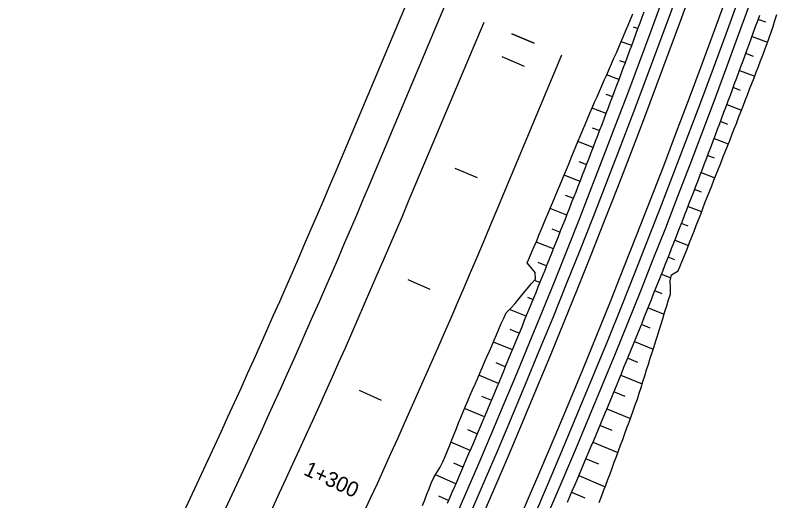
# Model space of a CAD drawing. Extents: x 6503541 to 6503743, y 5888004 to 5888145.
# Drawn here: x 6503701.128 to 6503702.659, y 5888111.328 to 5888112.29 of the extents above; entities that cross this region are included whole.
import ezdxf

# ---------------------------------------------------------------- set-up
doc = ezdxf.new("R2010")
doc.units = 0
doc.layers.add('12', color=7, linetype='Continuous')

msp = doc.modelspace()

# ---------------------------------------------------------------- linework, layer by layer
at = {"layer": '12'}
for p, q in [((6503701.7627, 5888111.9819), (6503701.9121, 5888112.3369)), ((6503701.829, 5888111.954), (6503701.9785, 5888112.309)), ((6503701.9064, 5888111.9214), (6503702.0561, 5888112.2767)), ((6503702.614, 5888112.2766), (6503702.5989, 5888112.2821)), ((6503702.3512, 5888112.2675), (6503702.3608, 5888112.264)), ((6503702.5866, 5888112.2482), (6503702.6174, 5888112.237)), ((6503702.3483, 5888112.2302), (6503702.3275, 5888112.2379)), ((6503702.08, 5888111.9008), (6503702.21, 5888112.2118)), ((6503702.5895, 5888112.2088), (6503702.5742, 5888112.2144)), ((6503702.3244, 5888112.2007), (6503702.3357, 5888112.1965)), ((6503702.5618, 5888112.1806), (6503702.5919, 5888112.1695)), ((6503702.3231, 5888112.1627), (6503702.2986, 5888112.1719)), ((6503702.2973, 5888112.134), (6503702.3105, 5888112.1291)), ((6503702.5641, 5888112.1414), (6503702.5493, 5888112.1469)), ((6503702.2977, 5888112.0954), (6503702.2697, 5888112.106)), ((6503702.5367, 5888112.1131), (6503702.5658, 5888112.1023)), ((6503702.5384, 5888112.074), (6503702.5241, 5888112.0794)), ((6503702.2702, 5888112.0674), (6503702.2849, 5888112.0617)), ((6503702.5114, 5888112.0457), (6503702.5396, 5888112.0351)), ((6503702.272, 5888112.0281), (6503702.2418, 5888112.0397)), ((6503702.5125, 5888112.0068), (6503702.4987, 5888112.0121)), ((6503702.2436, 5888112.0005), (6503702.2591, 5888111.9945)), ((6503702.246, 5888111.961), (6503702.2144, 5888111.9733)), ((6503702.4858, 5888111.9784), (6503702.513, 5888111.968)), ((6503702.4863, 5888111.9397), (6503702.4729, 5888111.9448)), ((6503702.2168, 5888111.9337), (6503702.233, 5888111.9274)), ((6503702.2198, 5888111.8939), (6503702.1868, 5888111.9069)), ((6503702.46, 5888111.9112), (6503702.4867, 5888111.9009)), ((6503702.4604, 5888111.8724), (6503702.4469, 5888111.8777)), ((6503702.1898, 5888111.8671), (6503702.2066, 5888111.8604)), ((6503702.4339, 5888111.8441), (6503702.4607, 5888111.8336)), ((6503702.1933, 5888111.827), (6503702.159, 5888111.8406)), ((6503702.1625, 5888111.8005), (6503702.1799, 5888111.7935)), ((6503702.434, 5888111.8054), (6503702.4207, 5888111.8106)), ((6503702.4075, 5888111.7771), (6503702.426, 5888111.7698)), ((6503702.1665, 5888111.7601), (6503702.1555, 5888111.7646)), ((6503702.4087, 5888111.7379), (6503702.3942, 5888111.7437)), ((6503702.1421, 5888111.7312), (6503702.153, 5888111.7268)), ((6503702.1395, 5888111.6934), (6503702.1063, 5888111.7069)), ((6503702.3808, 5888111.7103), (6503702.4126, 5888111.6975)), ((6503702.3846, 5888111.6699), (6503702.3674, 5888111.6769)), ((6503702.1072, 5888111.6677), (6503702.1258, 5888111.6601)), ((6503702.3539, 5888111.6435), (6503702.391, 5888111.6284)), ((6503702.1122, 5888111.6268), (6503702.0743, 5888111.6424)), ((6503702.0792, 5888111.6015), (6503702.0984, 5888111.5935)), ((6503702.3602, 5888111.602), (6503702.3403, 5888111.6101)), ((6503702.0846, 5888111.5603), (6503702.0456, 5888111.5765)), ((6503702.3267, 5888111.5768), (6503702.3691, 5888111.5594)), ((6503702.3355, 5888111.5342), (6503702.313, 5888111.5435)), ((6503702.051, 5888111.5353), (6503702.0707, 5888111.5271)), ((6503702.0567, 5888111.4939), (6503702.0172, 5888111.5106)), ((6503702.2993, 5888111.5102), (6503702.3458, 5888111.4909)), ((6503702.3094, 5888111.467), (6503702.2854, 5888111.477)), ((6503702.0232, 5888111.469), (6503702.0427, 5888111.4607)), ((6503702.0286, 5888111.4276), (6503701.9903, 5888111.444)), ((6503702.2716, 5888111.4438), (6503702.3209, 5888111.4231)), ((6503701.9956, 5888111.4026), (6503702.0145, 5888111.3945)), ((6503702.283, 5888111.3999), (6503702.2576, 5888111.4106)), ((6503702.0002, 5888111.3614), (6503701.9596, 5888111.379)), ((6503702.2436, 5888111.3775), (6503702.2957, 5888111.3553)), ((6503701.9655, 5888111.3373), (6503701.9859, 5888111.3284)), ((6503702.2561, 5888111.333), (6503702.2295, 5888111.3443))]:
    msp.add_line(p, q, dxfattribs=at)
for points in [[(6503701.9342, 5888111.3183), (6503701.9384, 5888111.3295), (6503701.9428, 5888111.3406), (6503701.9473, 5888111.3516), (6503701.9514, 5888111.3628), (6503701.9563, 5888111.3736), (6503701.9625, 5888111.3839), (6503701.9687, 5888111.3942), (6503701.9744, 5888111.4047), (6503701.9788, 5888111.4157), (6503701.9833, 5888111.4268), (6503701.9878, 5888111.4378), (6503701.9923, 5888111.4488), (6503701.9967, 5888111.4598), (6503702.0012, 5888111.4709), (6503702.0056, 5888111.4819), (6503702.0101, 5888111.493), (6503702.0145, 5888111.504), (6503702.0191, 5888111.515), (6503702.0237, 5888111.526), (6503702.0285, 5888111.5369), (6503702.0333, 5888111.5478), (6503702.038, 5888111.5586), (6503702.0427, 5888111.5696), (6503702.0473, 5888111.5806), (6503702.0521, 5888111.5915), (6503702.0569, 5888111.6024), (6503702.0617, 5888111.6133), (6503702.0664, 5888111.6242), (6503702.0711, 5888111.6351), (6503702.0759, 5888111.646), (6503702.0806, 5888111.6569), (6503702.0853, 5888111.6679), (6503702.09, 5888111.6788), (6503702.0948, 5888111.6897), (6503702.0995, 5888111.7006), (6503702.1092, 5888111.7096), (6503702.1172, 5888111.7191), (6503702.1253, 5888111.7287), (6503702.1334, 5888111.7383), (6503702.1414, 5888111.7479), (6503702.1495, 5888111.7575), (6503702.1576, 5888111.7671), (6503702.1568, 5888111.7802), (6503702.1415, 5888111.7992), (6503702.1461, 5888111.8102), (6503702.1508, 5888111.8211), (6503702.1554, 5888111.8321), (6503702.1601, 5888111.8431), (6503702.1646, 5888111.854), (6503702.1693, 5888111.865), (6503702.1739, 5888111.876), (6503702.1785, 5888111.887), (6503702.1831, 5888111.8979), (6503702.1877, 5888111.9089), (6503702.1923, 5888111.9199), (6503702.1969, 5888111.9309), (6503702.2014, 5888111.9419), (6503702.206, 5888111.9529), (6503702.2105, 5888111.9639), (6503702.2151, 5888111.9749), (6503702.2196, 5888111.9859), (6503702.2242, 5888111.9969), (6503702.2287, 5888112.0079), (6503702.2332, 5888112.0189), (6503702.2378, 5888112.03), (6503702.2423, 5888112.041), (6503702.2468, 5888112.052), (6503702.2514, 5888112.063), (6503702.2559, 5888112.074), (6503702.2605, 5888112.085), (6503702.2652, 5888112.096), (6503702.27, 5888112.1069), (6503702.2749, 5888112.1178), (6503702.2797, 5888112.1287), (6503702.2844, 5888112.1396), (6503702.2892, 5888112.1505), (6503702.294, 5888112.1614), (6503702.2988, 5888112.1724), (6503702.3037, 5888112.1833), (6503702.3084, 5888112.1942), (6503702.3131, 5888112.2052), (6503702.3179, 5888112.2161), (6503702.3227, 5888112.227), (6503702.3275, 5888112.238), (6503702.3323, 5888112.2489), (6503702.337, 5888112.2598), (6503702.3415, 5888112.2709), (6503702.346, 5888112.2819), (6503702.3505, 5888112.2929)], [(6503701.9836, 5888111.3229), (6503701.9883, 5888111.3338), (6503701.993, 5888111.3448), (6503701.9978, 5888111.3557), (6503702.0025, 5888111.3667), (6503702.0072, 5888111.3776), (6503702.0119, 5888111.3886), (6503702.0166, 5888111.3995), (6503702.0213, 5888111.4105), (6503702.026, 5888111.4215), (6503702.0307, 5888111.4324), (6503702.0354, 5888111.4434), (6503702.04, 5888111.4544), (6503702.0447, 5888111.4654), (6503702.0493, 5888111.4763), (6503702.054, 5888111.4873), (6503702.0586, 5888111.4983), (6503702.0632, 5888111.5093), (6503702.0679, 5888111.5203), (6503702.0725, 5888111.5313), (6503702.0771, 5888111.5423), (6503702.0817, 5888111.5533), (6503702.0863, 5888111.5643), (6503702.0909, 5888111.5753), (6503702.0954, 5888111.5864), (6503702.1, 5888111.5974), (6503702.1046, 5888111.6084), (6503702.1091, 5888111.6194), (6503702.1137, 5888111.6304), (6503702.1182, 5888111.6415), (6503702.1227, 5888111.6525), (6503702.1273, 5888111.6635), (6503702.1318, 5888111.6746), (6503702.1363, 5888111.6856), (6503702.1408, 5888111.6967), (6503702.1453, 5888111.7077), (6503702.1498, 5888111.7188), (6503702.1543, 5888111.7298), (6503702.1588, 5888111.7409), (6503702.1632, 5888111.7519), (6503702.1677, 5888111.763), (6503702.1721, 5888111.7741), (6503702.1766, 5888111.7851), (6503702.181, 5888111.7962), (6503702.1854, 5888111.8073), (6503702.1899, 5888111.8183), (6503702.1943, 5888111.8294), (6503702.1987, 5888111.8405), (6503702.2031, 5888111.8516), (6503702.2075, 5888111.8627), (6503702.2119, 5888111.8738), (6503702.2163, 5888111.8849), (6503702.2206, 5888111.896), (6503702.225, 5888111.9071), (6503702.2293, 5888111.9182), (6503702.2337, 5888111.9293), (6503702.238, 5888111.9404), (6503702.2424, 5888111.9515), (6503702.2467, 5888111.9626), (6503702.251, 5888111.9737), (6503702.2553, 5888111.9849), (6503702.2596, 5888111.996), (6503702.2639, 5888112.0071), (6503702.2682, 5888112.0182), (6503702.2725, 5888112.0294), (6503702.2768, 5888112.0405), (6503702.281, 5888112.0516), (6503702.2853, 5888112.0628), (6503702.2896, 5888112.0739), (6503702.2938, 5888112.0851), (6503702.298, 5888112.0962), (6503702.3023, 5888112.1074), (6503702.3065, 5888112.1185), (6503702.3107, 5888112.1297), (6503702.3149, 5888112.1408), (6503702.3191, 5888112.152), (6503702.3233, 5888112.1632), (6503702.3275, 5888112.1743), (6503702.3317, 5888112.1855), (6503702.3358, 5888112.1967), (6503702.34, 5888112.2079), (6503702.3442, 5888112.219), (6503702.3483, 5888112.2302), (6503702.3524, 5888112.2414), (6503702.3566, 5888112.2526), (6503702.3607, 5888112.2638), (6503702.3648, 5888112.275), (6503702.3689, 5888112.2862), (6503702.373, 5888112.2974)], [(6503702.2212, 5888111.325), (6503702.226, 5888111.3361), (6503702.2307, 5888111.3472), (6503702.2354, 5888111.3583), (6503702.2402, 5888111.3694), (6503702.2449, 5888111.3805), (6503702.2496, 5888111.3916), (6503702.2543, 5888111.4028), (6503702.259, 5888111.4139), (6503702.2637, 5888111.425), (6503702.2683, 5888111.4361), (6503702.273, 5888111.4473), (6503702.2777, 5888111.4584), (6503702.2823, 5888111.4695), (6503702.287, 5888111.4807), (6503702.2916, 5888111.4918), (6503702.2962, 5888111.503), (6503702.3009, 5888111.5141), (6503702.3055, 5888111.5253), (6503702.3101, 5888111.5364), (6503702.3147, 5888111.5476), (6503702.3193, 5888111.5588), (6503702.3239, 5888111.5699), (6503702.3285, 5888111.5811), (6503702.333, 5888111.5923), (6503702.3376, 5888111.6034), (6503702.3422, 5888111.6146), (6503702.3467, 5888111.6258), (6503702.3513, 5888111.637), (6503702.3558, 5888111.6482), (6503702.3603, 5888111.6594), (6503702.3649, 5888111.6706), (6503702.3694, 5888111.6818), (6503702.3739, 5888111.693), (6503702.3784, 5888111.7042), (6503702.3829, 5888111.7154), (6503702.3873, 5888111.7266), (6503702.3918, 5888111.7378), (6503702.3963, 5888111.749), (6503702.4008, 5888111.7602), (6503702.4052, 5888111.7714), (6503702.4097, 5888111.7827), (6503702.4141, 5888111.7939), (6503702.4185, 5888111.8051), (6503702.423, 5888111.8163), (6503702.4274, 5888111.8276), (6503702.4318, 5888111.8388), (6503702.4362, 5888111.8501), (6503702.4406, 5888111.8613), (6503702.445, 5888111.8726), (6503702.4493, 5888111.8838), (6503702.4537, 5888111.8951), (6503702.4581, 5888111.9063), (6503702.4624, 5888111.9176), (6503702.4668, 5888111.9288), (6503702.4711, 5888111.9401), (6503702.4755, 5888111.9514), (6503702.4798, 5888111.9626), (6503702.4841, 5888111.9739), (6503702.4884, 5888111.9852), (6503702.4927, 5888111.9965), (6503702.497, 5888112.0077), (6503702.5013, 5888112.019), (6503702.5056, 5888112.0303), (6503702.5099, 5888112.0416), (6503702.5141, 5888112.0529), (6503702.5184, 5888112.0642), (6503702.5226, 5888112.0755), (6503702.5269, 5888112.0868), (6503702.5311, 5888112.0981), (6503702.5354, 5888112.1094), (6503702.5396, 5888112.1207), (6503702.5438, 5888112.132), (6503702.548, 5888112.1434), (6503702.5522, 5888112.1547), (6503702.5564, 5888112.166), (6503702.5606, 5888112.1773), (6503702.5647, 5888112.1886), (6503702.5689, 5888112.2), (6503702.5731, 5888112.2113), (6503702.5772, 5888112.2226), (6503702.5814, 5888112.234), (6503702.5855, 5888112.2453), (6503702.5896, 5888112.2567), (6503702.5938, 5888112.268), (6503702.5979, 5888112.2794), (6503702.602, 5888112.2907)], [(6503702.2841, 5888111.3244), (6503702.2884, 5888111.3358), (6503702.2926, 5888111.3471), (6503702.2969, 5888111.3585), (6503702.3011, 5888111.3698), (6503702.3054, 5888111.3812), (6503702.3096, 5888111.3925), (6503702.3138, 5888111.4039), (6503702.318, 5888111.4153), (6503702.3222, 5888111.4266), (6503702.3264, 5888111.438), (6503702.3306, 5888111.4494), (6503702.3348, 5888111.4608), (6503702.3389, 5888111.4721), (6503702.3431, 5888111.4835), (6503702.3473, 5888111.4949), (6503702.3514, 5888111.5063), (6503702.3555, 5888111.5177), (6503702.3595, 5888111.5292), (6503702.3632, 5888111.5407), (6503702.3669, 5888111.5523), (6503702.3705, 5888111.5639), (6503702.3742, 5888111.5754), (6503702.3779, 5888111.587), (6503702.3816, 5888111.5986), (6503702.3852, 5888111.6101), (6503702.3889, 5888111.6217), (6503702.3925, 5888111.6333), (6503702.3962, 5888111.6449), (6503702.3998, 5888111.6565), (6503702.4034, 5888111.668), (6503702.407, 5888111.6796), (6503702.4106, 5888111.6912), (6503702.4142, 5888111.7028), (6503702.4178, 5888111.7144), (6503702.4214, 5888111.726), (6503702.425, 5888111.7376), (6503702.4254, 5888111.7504), (6503702.4244, 5888111.7638), (6503702.4274, 5888111.7756), (6503702.4405, 5888111.7835), (6503702.445, 5888111.7947), (6503702.4496, 5888111.8059), (6503702.4541, 5888111.8171), (6503702.4586, 5888111.8283), (6503702.4631, 5888111.8395), (6503702.4675, 5888111.8508), (6503702.4719, 5888111.8621), (6503702.4763, 5888111.8733), (6503702.4807, 5888111.8846), (6503702.4849, 5888111.8959), (6503702.489, 5888111.9073), (6503702.4933, 5888111.9186), (6503702.4978, 5888111.9298), (6503702.5023, 5888111.9411), (6503702.5068, 5888111.9523), (6503702.5113, 5888111.9635), (6503702.5157, 5888111.9748), (6503702.5202, 5888111.986), (6503702.5246, 5888111.9972), (6503702.5291, 5888112.0085), (6503702.5335, 5888112.0197), (6503702.538, 5888112.031), (6503702.5424, 5888112.0422), (6503702.5468, 5888112.0535), (6503702.5512, 5888112.0648), (6503702.5556, 5888112.076), (6503702.56, 5888112.0873), (6503702.5644, 5888112.0986), (6503702.5688, 5888112.1098), (6503702.5732, 5888112.1211), (6503702.5775, 5888112.1324), (6503702.5819, 5888112.1437), (6503702.5862, 5888112.155), (6503702.5906, 5888112.1662), (6503702.5949, 5888112.1775), (6503702.5993, 5888112.1888), (6503702.6036, 5888112.2001), (6503702.6079, 5888112.2114), (6503702.6122, 5888112.2227), (6503702.6163, 5888112.2341), (6503702.6203, 5888112.2455), (6503702.6247, 5888112.2568), (6503702.6283, 5888112.2683), (6503702.6319, 5888112.2799), (6503702.6355, 5888112.2915)], [(6503702.1108, 5888112.2534), (6503702.1551, 5888112.2348)], [(6503702.1551, 5888112.2348), (6503702.1108, 5888112.2534)], [(6503702.1359, 5888112.189), (6503702.0916, 5888112.2076)], [(6503702.043, 5888111.9677), (6503701.9987, 5888111.9863)], [(6503701.9493, 5888111.7465), (6503701.9053, 5888111.7655)], [(6503701.8528, 5888111.5264), (6503701.809, 5888111.546)]]:
    msp.add_lwpolyline(points, dxfattribs=at)
for centre, radius, start, end in [((6503685.5719, 5888118.4473), 17.9412, 322.48762, 351.89568), ((6503685.5719, 5888118.4473), 17.9172, 324.73339, 351.89568), ((6503685.5719, 5888118.4473), 17.9652, 322.48762, 351.89568), ((6503685.5719, 5888118.4473), 18.0348, 322.48762, 351.89568), ((6503685.5719, 5888118.4473), 18.0588, 322.48762, 351.89568), ((6503685.5719, 5888118.4473), 18.0828, 324.58652, 351.89568), ((6503685.3946, 5888118.8742), 17.76, 330.69658, 337.1649), ((6503685.3946, 5888118.8742), 17.832, 330.69658, 337.1649), ((6503685.3946, 5888118.8742), 17.916, 330.69658, 337.1649), ((6503685.3946, 5888118.8742), 18.084, 330.69648, 337.31833)]:
    msp.add_arc(centre, radius, start, end, dxfattribs=at)

# ---------------------------------------------------------------- texts
msp.add_text('1+300', height=0.03, rotation=335.1776, dxfattribs=at).set_placement((6503701.6967, 5888111.3801))

doc.saveas('drawing.dxf')
